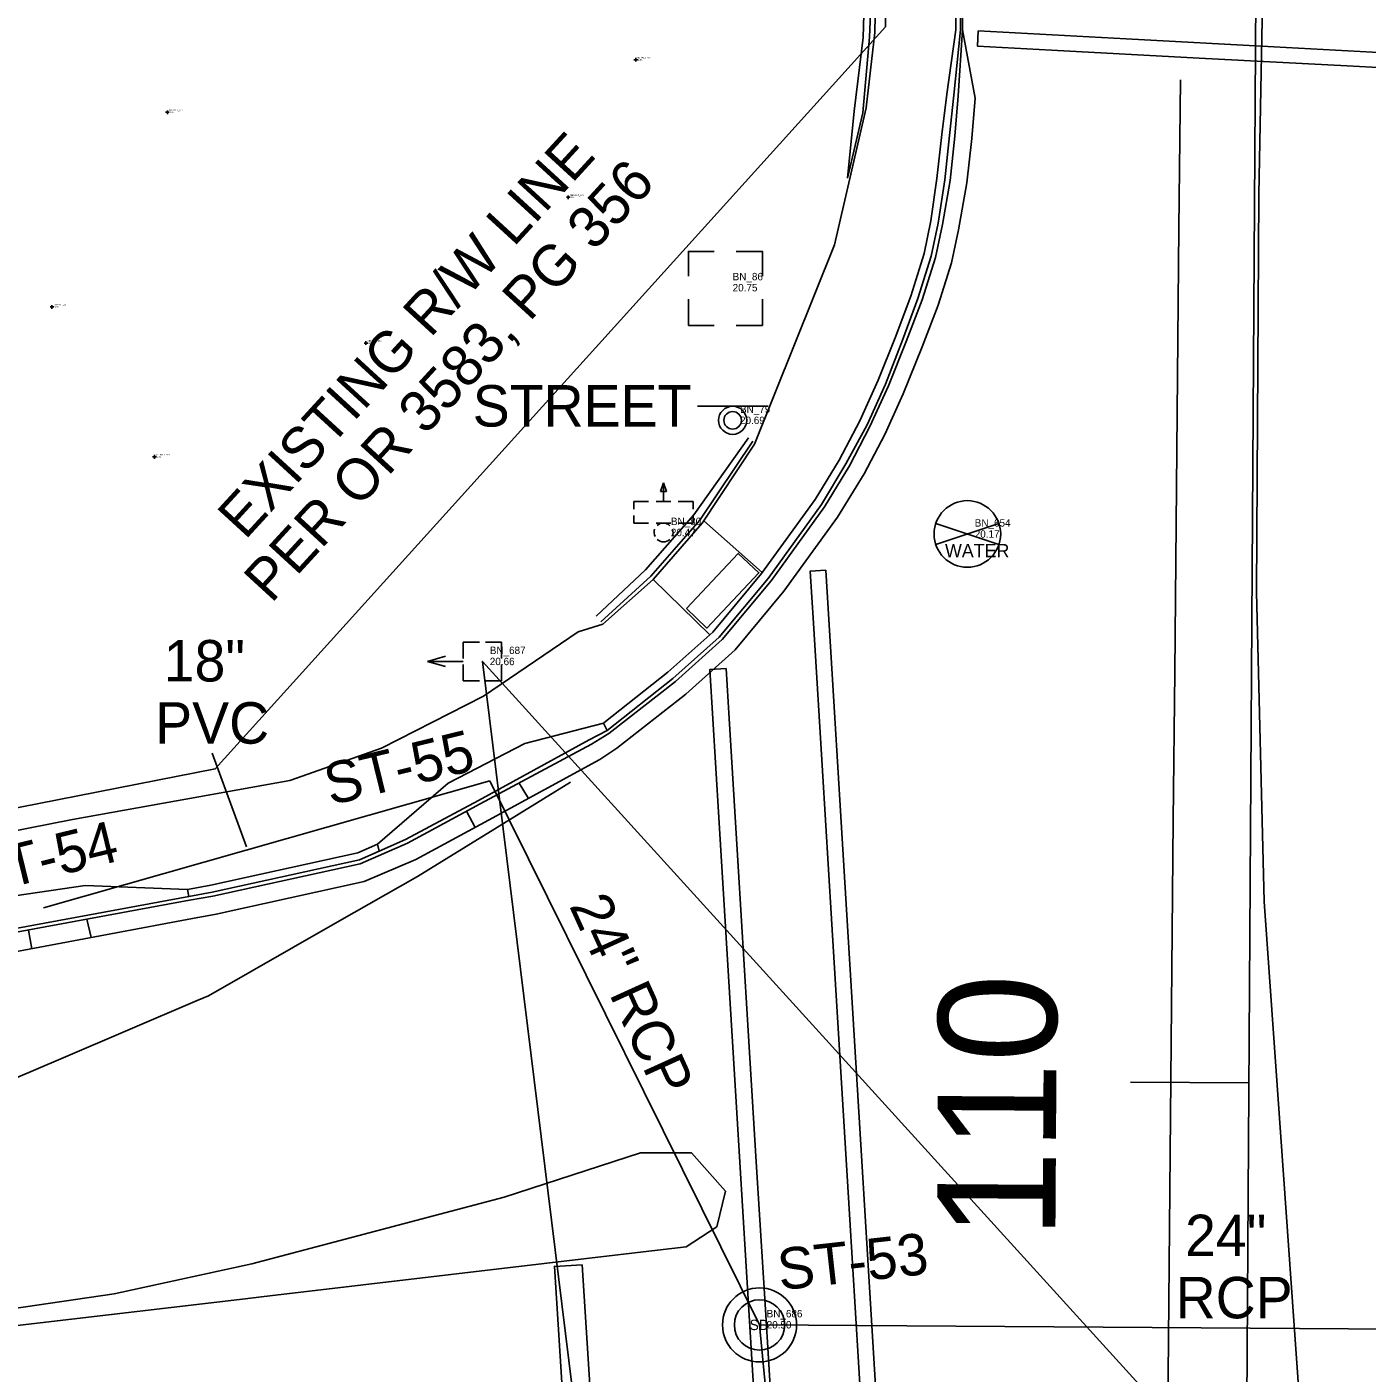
# Model space of a CAD drawing. Extents: x 509744 to 512285, y 1314862 to 1316822.
# Drawn here: x 510403.6 to 510494.1, y 1315985.3 to 1316076.2 of the extents above; entities that cross this region are included whole.
import ezdxf

# ---------------------------------------------------------------- set-up
doc = ezdxf.new("R2010")
doc.units = 0
for name, color, linetype in [('AccessRamp_ep', 7, 'Continuous'), ('BaselineSurvey', 7, 'Continuous'), ('CatchBasin_ep', 7, 'Continuous'), ('CGBack_ep', 7, 'Continuous'), ('CGep_ep', 7, 'Continuous'), ('CGFace_ep', 7, 'Continuous'), ('CurbRampWarning_ep', 7, 'Continuous'), ('ElecAer_ep', 7, 'Continuous'), ('GroundShot_ep', 7, 'Continuous'), ('InletCurb_ep', 7, 'Continuous'), ('ManholeSW_ep', 7, 'Continuous'), ('NonPlottingEle_dp', 7, 'Continuous'), ('PavtAsphalt_ep', 7, 'Continuous'), ('PavtAsphaltCrown_ep', 7, 'Continuous'), ('PavtBreak_ep', 7, 'Continuous'), ('PedSignal_ep', 7, 'Continuous'), ('PipeCulvert_ep', 7, 'Continuous'), ('PMRK_ep', 7, 'Continuous'), ('PullBox_ep', 7, 'Continuous'), ('RWLine_ep', 7, 'Continuous'), ('SidewalkBack_ep', 7, 'Continuous'), ('SignSingle_ep', 7, 'Continuous'), ('SpanWireP_ep', 7, 'Continuous'), ('TextElevLabel', 7, 'Continuous'), ('TextNotes', 7, 'Continuous'), ('TextPtLabel', 7, 'Continuous'), ('TextTopoLabel_ep', 7, 'Continuous'), ('ValveCvrWater_ep', 7, 'Continuous')]:
    doc.layers.add(name, color=color, linetype=linetype)

msp = doc.modelspace()

# ---------------------------------------------------------------- linework, layer by layer
at = {"layer": 'AccessRamp_ep'}
for p, q in [((510453.248, 1316039.384), (510449.295, 1316042.882)), ((510449.712, 1316035.192), (510445.875, 1316038.925))]:
    msp.add_line(p, q, dxfattribs=at)
at = {"layer": 'BaselineSurvey'}
for p, q in [((510484.134, 1315694.907), (510491.264, 1316815.908)), ((510486.106, 1316004.924), (510478.106, 1316004.975))]:
    msp.add_line(p, q, dxfattribs=at)
at = {"layer": 'CatchBasin_ep'}
for p, q in [((510436.824, 1316025.17), (510437.452, 1316024.13)), ((510433.281, 1316023.265), (510433.856, 1316022.167)), ((510407.636, 1316015.976), (510407.926, 1316014.738)), ((510403.696, 1316015.248), (510403.931, 1316013.986))]:
    msp.add_line(p, q, dxfattribs=at)
at = {"layer": 'CGBack_ep'}
msp.add_line((510459.451, 1316070.54), (510458.996, 1316066.032), dxfattribs=at)
for points in [[(510442.547, 1316029.236), (510446.866, 1316032.67), (510449.909, 1316035.367), (510453.205, 1316039.324), (510456.816, 1316044.322), (510458.442, 1316046.976), (510459.827, 1316049.637), (510461.073, 1316052.374), (510462.23, 1316055.25), (510463.271, 1316058.065), (510464.177, 1316060.925), (510464.639, 1316063.149), (510465.028, 1316065.995), (510465.37, 1316068.977), (510465.718, 1316071.696), (510466.321, 1316076.042), (510466.322, 1316082.478), (510466.337, 1316085.675), (510466.321, 1316090.37), (510466.479, 1316120.365), (510466.635, 1316150.365), (510466.81, 1316180.364), (510466.819, 1316186.364), (510466.827, 1316192.515)], [(510459.451, 1316070.54), (510460.061, 1316075.53), (510460.385, 1316086.353), (510460.361, 1316088.932)], [(510452.31, 1316048.479), (510448.621, 1316043.28), (510445.36, 1316039.582), (510442.031, 1316036.444)], [(510414.43, 1316017.986), (510416.007, 1316018.276), (510425.939, 1316020.462), (510427.265, 1316021.042)]]:
    msp.add_lwpolyline(points, dxfattribs=at)
at = {"layer": 'CGep_ep'}
msp.add_lwpolyline([(510397.981, 1316014.193), (510414.561, 1316017.254), (510416.141, 1316017.533), (510426.097, 1316019.723), (510429.285, 1316021.11), (510434.202, 1316023.761), (510441.714, 1316027.798), (510442.894, 1316028.523), (510447.38, 1316032.039), (510450.549, 1316034.863), (510453.845, 1316038.821), (510457.456, 1316043.818), (510459.131, 1316046.601), (510460.517, 1316049.262), (510461.763, 1316051.999), (510462.968, 1316055.002), (510464.042, 1316057.806), (510464.949, 1316060.666), (510465.41, 1316062.889), (510465.928, 1316065.87), (510466.253, 1316068.854), (510466.484, 1316071.59), (510466.758, 1316076.036)], dxfattribs=at)
at = {"layer": 'CGFace_ep'}
for points in [[(510460.361, 1316088.932), (510460.931, 1316086.329), (510460.493, 1316075.549), (510460.033, 1316070.442), (510458.996, 1316066.032)], [(510442.774, 1316028.727), (510442.781, 1316028.73), (510447.213, 1316032.245), (510450.341, 1316035.027), (510453.636, 1316038.985), (510457.247, 1316043.982), (510458.898, 1316046.728), (510460.32, 1316049.369), (510461.56, 1316052.109), (510462.717, 1316055.086), (510463.752, 1316057.903), (510464.658, 1316060.764), (510465.12, 1316062.987), (510465.571, 1316065.92), (510465.879, 1316068.906), (510466.185, 1316071.632), (510466.623, 1316076.038), (510466.624, 1316082.474)], [(510442.351, 1316036.062), (510445.712, 1316039.154), (510449.021, 1316042.936), (510452.603, 1316048.26)], [(510414.514, 1316017.516), (510416.092, 1316017.806), (510426.039, 1316019.994), (510427.37, 1316020.573)]]:
    msp.add_lwpolyline(points, dxfattribs=at)
at = {"layer": 'CurbRampWarning_ep'}
msp.add_lwpolyline([(510448.12, 1316036.951), (510451.629, 1316040.684), (510453.022, 1316039.375), (510449.514, 1316035.642)], close=True, dxfattribs=at)
at = {"layer": 'ElecAer_ep'}
msp.add_lwpolyline([(510447.916, 1315923.604), (510519.717, 1315939.401), (510434.348, 1316033.385), (510447.882, 1315923.851)], dxfattribs=at)
at = {"layer": 'GroundShot_ep'}
for p, q in [((510444.825, 1316074.016), (510444.575, 1316074.016)), ((510444.7, 1316073.891), (510444.7, 1316074.141)), ((510413.198, 1316070.473), (510412.948, 1316070.473)), ((510413.073, 1316070.348), (510413.073, 1316070.598)), ((510440.273, 1316064.729), (510440.023, 1316064.729)), ((510440.148, 1316064.604), (510440.148, 1316064.854)), ((510405.402, 1316057.327), (510405.152, 1316057.327)), ((510405.277, 1316057.202), (510405.277, 1316057.452)), ((510426.486, 1316054.759), (510426.486, 1316055.009)), ((510426.611, 1316054.884), (510426.361, 1316054.884)), ((510412.323, 1316047.204), (510412.073, 1316047.204)), ((510412.198, 1316047.079), (510412.198, 1316047.329))]:
    msp.add_line(p, q, dxfattribs=at)
at = {"layer": 'InletCurb_ep'}
msp.add_lwpolyline([(510427.37, 1316020.573), (510427.265, 1316021.042), (510432.034, 1316025.165), (510437.207, 1316027.834), (510442.518, 1316029.212), (510442.781, 1316028.73), (510441.55, 1316028.098), (510434.079, 1316024.003), (510429.162, 1316021.352)], close=True, dxfattribs=at)
msp.add_lwpolyline([(510397.936, 1316014.443), (510414.514, 1316017.516), (510414.43, 1316017.986), (510407.522, 1316018.262), (510402.764, 1316017.555), (510397.67, 1316015.332), (510397.863, 1316014.85)], dxfattribs=at)
at = {"layer": 'ManholeSW_ep'}
for radius in [2.5, 1.7]:
    msp.add_circle((510453.061, 1315988.58), radius, dxfattribs=at)
at = {"layer": 'NonPlottingEle_dp'}
msp.add_line((510416.106, 1316027.182), (510418.428, 1316020.875), dxfattribs=at)
at = {"layer": 'PavtAsphalt_ep'}
msp.add_lwpolyline([(510466.758, 1316082.473), (510466.758, 1316076.036), (510467.618, 1316071.433), (510467.387, 1316068.697), (510467.062, 1316065.713), (510466.495, 1316062.524), (510466.034, 1316060.301), (510465.128, 1316057.44), (510464.053, 1316054.637), (510462.769, 1316051.452), (510461.523, 1316048.715), (510460.137, 1316046.054), (510458.323, 1316043.135), (510454.712, 1316038.138), (510451.416, 1316034.18), (510448.078, 1316031.183), (510443.437, 1316027.529), (510442.274, 1316026.772), (510434.765, 1316022.657), (510429.848, 1316020.006), (510426.355, 1316018.517), (510416.36, 1316016.319), (510414.782, 1316016.029), (510398.212, 1316012.91)], dxfattribs=at)
at = {"layer": 'PavtAsphaltCrown_ep'}
msp.add_lwpolyline([(510487.857, 1316252.334), (510487.145, 1316228.217), (510487.802, 1316209.666), (510487.298, 1316196.938), (510487.463, 1316175.759), (510486.8, 1316155.464), (510487.041, 1316127.532), (510486.794, 1316112.305), (510487.178, 1316086.167), (510486.773, 1316064.916), (510486.628, 1316038.076), (510487.142, 1316017.171), (510489.752, 1315980.275)], dxfattribs=at)
at = {"layer": 'PavtBreak_ep'}
msp.add_lwpolyline([(510481.48, 1316072.655), (510481.384, 1316062.656), (510481.289, 1316052.656), (510481.194, 1316042.656), (510481.098, 1316032.657), (510481.003, 1316022.657), (510480.908, 1316012.658), (510480.812, 1316002.658), (510480.717, 1315992.659), (510480.622, 1315982.659), (510480.526, 1315972.66), (510480.431, 1315962.66), (510480.336, 1315952.661), (510480.24, 1315942.661), (510480.223, 1315940.852)], dxfattribs=at)
at = {"layer": 'PedSignal_ep'}
for p, q in [((510446.572, 1316045.458), (510446.374, 1316044.858)), ((510446.572, 1316044.183), (510446.572, 1316045.458)), ((510446.572, 1316045.458), (510446.77, 1316044.858)), ((510444.572, 1316044.183), (510445.572, 1316044.183)), ((510444.572, 1316044.183), (510444.572, 1316043.675)), ((510446.072, 1316044.183), (510447.072, 1316044.183)), ((510446.374, 1316044.858), (510446.77, 1316044.858)), ((510447.572, 1316044.183), (510448.572, 1316044.183)), ((510448.572, 1316044.183), (510448.572, 1316043.675)), ((510444.572, 1316043.24), (510444.572, 1316042.733)), ((510448.572, 1316043.24), (510448.572, 1316042.733)), ((510444.572, 1316042.733), (510445.572, 1316042.733)), ((510446.072, 1316042.733), (510447.072, 1316042.733)), ((510447.572, 1316042.733), (510448.572, 1316042.733))]:
    msp.add_line(p, q, dxfattribs=at)
for centre, radius, start, end in [((510446.715, 1316042.115), 0.766, 163.88316, 202.84976), ((510446.564, 1316042.117), 0.616, 45.06774, 132.92209), ((510446.789, 1316042.073), 0.437, 329.03624, 30.96376), ((510446.579, 1316042.075), 0.617, 227.10453, 312.89547)]:
    msp.add_arc(centre, radius, start, end, dxfattribs=at)
at = {"layer": 'PipeCulvert_ep'}
msp.add_line((510453.061, 1315988.58), (510502.341, 1315988.248), dxfattribs=at)
for points in [[(510404.702, 1316016.738), (510434.858, 1316025.334)], [(510434.858, 1316025.334), (510453.061, 1315988.58)], [(510453.061, 1315988.58), (510458.221, 1315934.794)]]:
    msp.add_lwpolyline(points, dxfattribs=at)
at = {"layer": 'PMRK_ep'}
for points in [[(510467.825, 1316075.965), (510477.811, 1316075.43), (510487.796, 1316074.894), (510497.782, 1316074.359), (510507.768, 1316073.823), (510512.768, 1316073.555), (510512.713, 1316072.531), (510502.728, 1316073.066), (510492.742, 1316073.602), (510482.756, 1316074.137), (510472.771, 1316074.673), (510467.77, 1316074.941), (510467.825, 1316075.965)], [(510460.352, 1315976.089), (510459.744, 1315986.071), (510459.135, 1315996.052), (510458.527, 1316006.034), (510457.919, 1316016.015), (510457.311, 1316025.997), (510456.702, 1316035.978), (510456.488, 1316039.491), (510457.534, 1316039.555)], [(510457.534, 1316039.555), (510458.142, 1316029.573), (510458.75, 1316019.592), (510459.359, 1316009.611), (510459.967, 1315999.629), (510460.575, 1315989.648), (510461.183, 1315979.666)], [(510454.065, 1315979.631), (510453.454, 1315989.612), (510452.844, 1315999.593), (510452.234, 1316009.575), (510451.624, 1316019.556), (510451.014, 1316029.537), (510450.808, 1316032.907), (510449.704, 1316032.839), (510450.314, 1316022.858), (510450.925, 1316012.876), (510451.535, 1316002.895), (510452.145, 1315992.914), (510452.755, 1315982.932)], [(510396.681, 1316002.64), (510405.879, 1316006.56), (510415.078, 1316010.48), (510415.861, 1316010.814), (510424.542, 1316015.773), (510429.965, 1316018.871), (510438.48, 1316024.113), (510440.292, 1316025.229)], [(510393.114, 1315987.385), (510417.943, 1315990.304), (510420.002, 1315990.546), (510444.831, 1315993.465), (510448.113, 1315993.851), (510450.176, 1315995.215), (510450.76, 1315997.618), (510448.477, 1316000.195), (510445.033, 1316000.195), (510435.821, 1315997.207), (510418.77, 1315992.696), (510409.479, 1315990.679), (510396.398, 1315988.77)]]:
    msp.add_lwpolyline(points, dxfattribs=at)
msp.add_lwpolyline([(510441.092, 1315992.647), (510443.264, 1315958.455), (510441.387, 1315958.336), (510439.215, 1315992.528)], close=True, dxfattribs=at)
at = {"layer": 'PullBox_ep'}
for points in [[(510449.993, 1316061.076), (510448.26, 1316061.076), (510448.26, 1316059.401)], [(510453.255, 1316059.401), (510453.255, 1316061.076), (510451.493, 1316061.076)], [(510448.26, 1316057.849), (510448.26, 1316056.076)], [(510451.493, 1316056.076), (510453.255, 1316056.076), (510453.255, 1316057.849)], [(510448.26, 1316056.076), (510449.993, 1316056.076)]]:
    msp.add_lwpolyline(points, dxfattribs=at)
at = {"layer": 'RWLine_ep'}
msp.add_line((510461.559, 1316076.237), (510462.928, 1316291.567), dxfattribs=at)
msp.add_lwpolyline([(510461.559, 1316076.237), (510416.313, 1316026.127), (510236.177, 1315990.718), (510118.392, 1315975.872)], dxfattribs=at)
at = {"layer": 'SidewalkBack_ep'}
msp.add_lwpolyline([(510460.929, 1316080.473), (510460.837, 1316075.852), (510460.255, 1316070.771), (510458.118, 1316061.513), (510452.725, 1316048.06), (510449.198, 1316042.735), (510445.881, 1316038.931), (510442.471, 1316035.909), (510440.814, 1316035.395), (510434.42, 1316031.043), (510427.533, 1316027.523), (510421.35, 1316025.35), (510406.672, 1316022.719), (510394.649, 1316020.351), (510393.936, 1316022.603), (510359.994, 1316016.322), (510340.704, 1316012.419), (510300.068, 1316004.811), (510290.855, 1316002.886), (510287.035, 1316002.397), (510278.693, 1316001.728), (510278.553, 1316006.381), (510275.911, 1316006.447), (510227.548, 1316006.591)], dxfattribs=at)
at = {"layer": 'SignSingle_ep'}
msp.add_line((510448.87, 1316050.62), (510453.62, 1316050.62), dxfattribs=at)
for radius in [0.95, 0.594]:
    msp.add_circle((510451.245, 1316049.67), radius, dxfattribs=at)
at = {"layer": 'SpanWireP_ep'}
for p, q in [((510433.048, 1316033.585), (510433.048, 1316034.685)), ((510433.048, 1316034.685), (510434.148, 1316034.685)), ((510434.548, 1316034.685), (510435.648, 1316034.685)), ((510435.648, 1316033.585), (510435.648, 1316034.685)), ((510430.648, 1316033.385), (510431.848, 1316033.735)), ((510430.648, 1316033.385), (510433.048, 1316033.385)), ((510430.648, 1316033.385), (510431.848, 1316033.035)), ((510433.048, 1316032.085), (510433.048, 1316033.185)), ((510435.648, 1316032.085), (510435.648, 1316033.185)), ((510433.048, 1316032.085), (510434.148, 1316032.085)), ((510434.548, 1316032.085), (510435.648, 1316032.085))]:
    msp.add_line(p, q, dxfattribs=at)
at = {"layer": 'ValveCvrWater_ep'}
for p, q in [((510464.96, 1316041.283), (510469.229, 1316042.706)), ((510469.229, 1316041.283), (510464.96, 1316042.706))]:
    msp.add_line(p, q, dxfattribs=at)
msp.add_circle((510467.095, 1316041.994), 2.25, dxfattribs=at)

# ---------------------------------------------------------------- texts
at = {"layer": 'BaselineSurvey'}
msp.add_text('110', height=8, rotation=89.63561, dxfattribs=at).set_placement((510473.039, 1315994.403))
at = {"layer": 'ManholeSW_ep'}
msp.add_text('SD', height=0.7, dxfattribs=at).set_placement((510452.388, 1315988.23))
at = {"layer": 'NonPlottingEle_dp'}
for s, p in [('18"', (510412.827, 1316032.032)), ('PVC', (510412.251, 1316027.832)), ('24"', (510481.796, 1315993.225)), ('RCP', (510481.159, 1315989.025))]:
    msp.add_text(s, height=2.8, dxfattribs=at).set_placement(p)
for s, rotation, p in [('ST-55', 13.81088, (510424.091, 1316023.653)), ('ST-54', 13.81088, (510400.032, 1316017.515)), ('24" RCP', 294.45303, (510440.183, 1316016.895)), ('ST-53', 6.33024, (510454.438, 1315990.918))]:
    msp.add_text(s, height=2.8, rotation=rotation, dxfattribs=at).set_placement(p)
at = {"layer": 'TextElevLabel'}
for s, height, p in [('21.66', 0.1, (510444.8, 1316073.966)), ('21.83', 0.1, (510413.173, 1316070.423)), ('21.62', 0.1, (510440.248, 1316064.679)), ('20.75', 0.5, (510451.247, 1316058.376)), ('21.99', 0.1, (510405.377, 1316057.277)), ('21.93', 0.1, (510426.586, 1316054.834)), ('20.69', 0.5, (510451.745, 1316049.42)), ('21.54', 0.1, (510412.298, 1316047.154)), ('20.47', 0.5, (510447.077, 1316041.845)), ('20.17', 0.5, (510467.595, 1316041.744)), ('20.66', 0.5, (510434.848, 1316033.135)), ('20.50', 0.5, (510453.545, 1315988.34))]:
    msp.add_text(s, height=height, dxfattribs=at).set_placement(p)
at = {"layer": 'TextNotes'}
for s, p in [('EXISTING R/W LINE ', (510418.324, 1316041.54)), ('PER OR 3583, PG 356', (510420.094, 1316037.254))]:
    msp.add_text(s, height=2.8, rotation=47.49415, dxfattribs=at).set_placement(p)
at = {"layer": 'TextPtLabel'}
for s, height, p in [('DEFAULT_654', 0.1, (510444.8, 1316074.116)), ('DEFAULT_657', 0.1, (510413.173, 1316070.573)), ('DEFAULT_653', 0.1, (510440.248, 1316064.829)), ('BN_86', 0.5, (510451.247, 1316059.126)), ('DEFAULT_658', 0.1, (510405.377, 1316057.427)), ('DEFAULT_652', 0.1, (510426.586, 1316054.984)), ('BN_79', 0.5, (510451.745, 1316050.17)), ('DEFAULT_651', 0.1, (510412.298, 1316047.304)), ('BN_80', 0.5, (510447.077, 1316042.595)), ('BN_654', 0.5, (510467.595, 1316042.494)), ('BN_687', 0.5, (510434.848, 1316033.885)), ('BN_686', 0.5, (510453.545, 1315989.09))]:
    msp.add_text(s, height=height, dxfattribs=at).set_placement(p)
at = {"layer": 'TextTopoLabel_ep'}
msp.add_text('STREET', height=2.8, dxfattribs=at).set_placement((510433.694, 1316049.248))
at = {"layer": 'ValveCvrWater_ep'}
msp.add_text('WATER', height=0.9, dxfattribs=at).set_placement((510465.587, 1316040.419))

doc.saveas('drawing.dxf')
